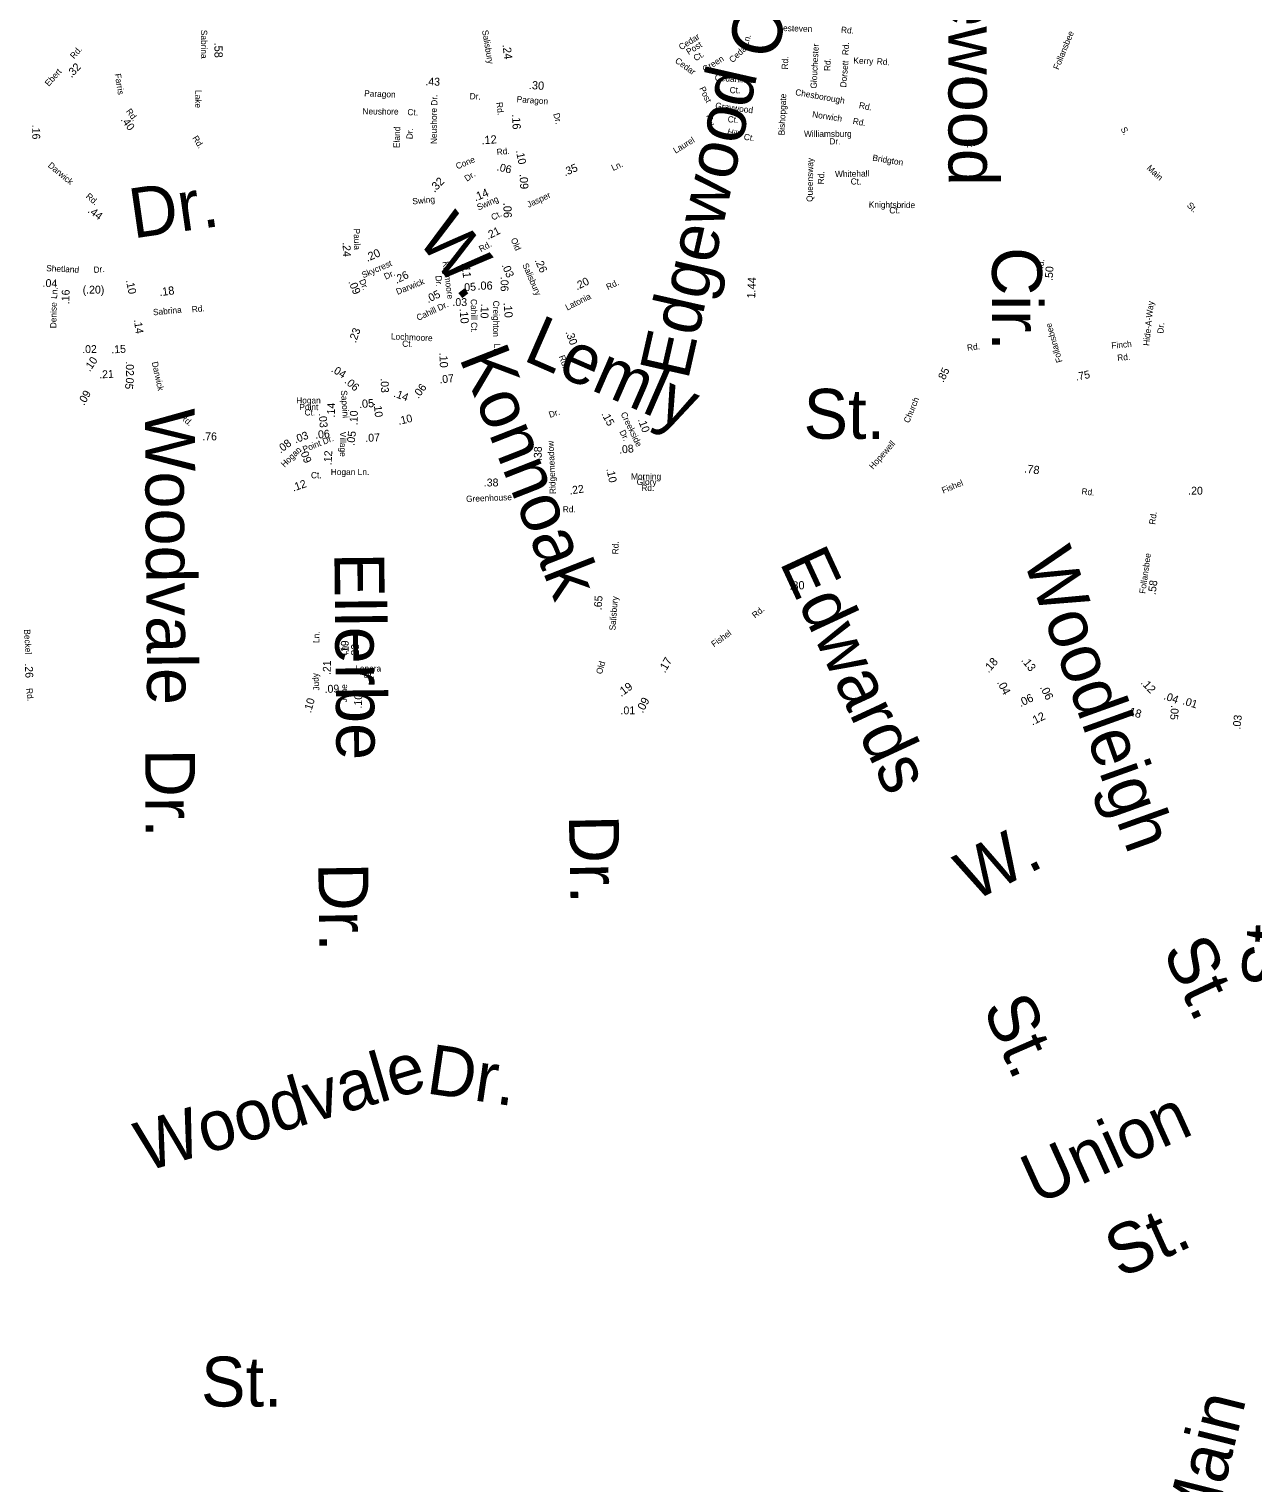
# Model space of a CAD drawing. Extents: x 1553981 to 1780076, y 812965 to 996873.
# Drawn here: x 1631447 to 1633779, y 842188 to 844957 of the extents above; entities that cross this region are included whole.
import ezdxf

# ---------------------------------------------------------------- set-up
doc = ezdxf.new("R2010")
doc.units = 0
for name, color, linetype in [('Exist Road Non-System Type 51 Label', 7, 'Continuous'), ('Exist Road Primary NC Service Mileage Hundredths English Label', 7, 'Continuous'), ('Exist Road Secondary Mileage Hundredths English Label', 7, 'Continuous'), ('Map Preparation Border Antique Large Shape', 7, 'Continuous')]:
    doc.layers.add(name, color=color, linetype=linetype)

msp = doc.modelspace()

# ---------------------------------------------------------------- texts
at = {"layer": 'Exist Road Non-System Type 51 Label'}
for s, height, rotation, p in [('Edgewood', 95, 270.0379, (1633198.2, 845258.6)), ('Cir.', 95, 77.2099, (1632869.8, 844896.5)), ('Kesteven', 11.87, 358.331, (1632872.6, 844953.4)), ('Cedar', 11.88, 32.0172, (1632689.2, 844916.4)), ('Ln.', 11.88, 73.5283, (1632816.3, 844923.9)), ('Rd.', 11.88, 356.1209, (1632993.4, 844949.8)), ('Follansbee', 11.87, 67.591, (1633408.3, 844878.5)), ('Post', 11.88, 32.0172, (1632703.4, 844907.3)), ('Ct.', 11.88, 32.0172, (1632717, 844895.3)), ('Cedar', 11.88, 42.9703, (1632787.1, 844891.9)), ('Glouchester', 11.875, 87.1504, (1632947.2, 844843.3)), ('Rd.', 11.87, 86.4361, (1633007.8, 844906.9)), ('Edgewood', 95, 77.2099, (1632702, 844286.7)), ('Cedar', 11.88, 324.0958, (1632676.3, 844894.2)), ('Green', 11.87, 31.5721, (1632734.3, 844874.3)), ('Rd.', 11.88, 87.5017, (1632892.4, 844879.8)), ('Rd.', 11.87, 87.1504, (1632973.1, 844876.8)), ('Dorsett', 11.88, 85.1235, (1633003.6, 844845.4)), ('Kerry', 11.88, 357.7706, (1633017.1, 844891.3)), ('Rd.', 11.88, 355.4178, (1633061.5, 844889.9)), ('Cedarlimb', 11.88, 355.783, (1632752.9, 844858.8)), ('Dr.', 11.88, 89.7738, (1632224.7, 844810.9)), ('Post', 11.88, 295.5736, (1632723.4, 844844)), ('Ct.', 11.87, 359.8343, (1632781.6, 844834.7)), ('Bishopgate', 11.88, 87.5649, (1632886.2, 844754.3)), ('Chesborough', 11.875, 349.9215, (1632905.9, 844831.3)), ('Neushore', 11.88, 359.7206, (1632081.9, 844794.4)), ('Ct.', 11.87, 357.8892, (1632167.4, 844793)), ('Neushore', 11.88, 89.9854, (1632223.7, 844737.8)), ('Graywood', 11.88, 352.7558, (1632753.6, 844805.5)), ('Norwich', 11.87, 351.2524, (1632938.2, 844789.1)), ('Rd.', 11.88, 348.3234, (1633027.1, 844806.6)), ('Rd.', 11.88, 277.3767, (1632737.1, 844792.8)), ('Ct.', 11.88, 356.0872, (1632777.5, 844779.5)), ('Rd.', 11.87, 349.9299, (1633015.4, 844776.3)), ('Eland', 11.88, 87.9801, (1632152.6, 844730.2)), ('Dr.', 11.88, 87.9801, (1632177.4, 844747)), ('Laurel', 11.88, 31.2119, (1632678.4, 844719.4)), ('Hill', 11.88, 343.6571, (1632775.9, 844756.6)), ('Ct.', 11.88, 351.978, (1632807.9, 844746.2)), ('Williamsburg', 11.875, 359.9662, (1632923.2, 844751.6)), ('Dr.', 11.88, 0.0292, (1632971.5, 844737.1)), ('Rd.', 11.88, 14.1286, (1633233.3, 844730.6)), ('S.', 11.88, 296.2999, (1633526.2, 844766.9)), ('Bridgton', 11.88, 350.7076, (1633052.9, 844706.4)), ('Queensway', 11.87, 89.1958, (1632939.8, 844627.7)), ('Whitehall', 11.88, 1.1444, (1632982.4, 844674.9)), ('Main', 11.88, 316.9743, (1633575.3, 844690.9)), ('Dr.', 95, 8.1495, (1631644.9, 844558)), ('Rd.', 11.87, 89.1958, (1632961.4, 844661.2)), ('Ct.', 11.88, 359.7089, (1633012.1, 844660.8)), ('W.', 95, 308.1143, (1632183.5, 844557.5)), ('Knightsbride', 11.875, 359.2377, (1633046.6, 844617)), ('Ct.', 11.88, 0.5122, (1633085.8, 844605.7)), ('St.', 11.88, 317.1411, (1633651.8, 844619.8)), ('Cir.', 95, 270.0379, (1633281.5, 844541.5)), ('Hide-A-Way', 11.88, 84.0485, (1633581, 844353.1)), ('Lemly', 95, 336.4005, (1632385.6, 844327)), ('Dr.', 11.88, 84.0485, (1633607.8, 844376.4)), ('Konnoak', 95, 291.3903, (1632265.6, 844331.1)), ('Finch', 11.87, 5.4278, (1633509.4, 844348)), ('Rd.', 11.87, 5.4278, (1633520.6, 844324.8)), ('St.', 95, 359.7227, (1632922.2, 844176.9)), ('Woodvale', 95, 270.4668, (1631667.3, 844234)), ('Edwards', 95, 294.7966, (1632875.8, 843941.6)), ('Woodleigh', 95, 289.7153, (1633339.7, 843947.9)), ('Ellerbe', 95, 270.6131, (1632028.4, 843959.4)), ('Dr.', 95, 270.2333, (1631668, 843586)), ('Dr.', 95, 271.1943, (1632475.1, 843459.2)), ('W.', 95, 26.6867, (1633244.5, 843293.8)), ('Dr.', 95, 270.7709, (1631997.7, 843368.6)), ('St.', 95, 87.3612, (1633851.6, 843128.7)), ('St.', 95, 295.054, (1633605.3, 843201.6)), ('St.', 95, 293.5348, (1633262.8, 843093.2)), ('Woodvale', 95, 16.4005, (1631667.1, 842779.8)), ('Dr.', 95, 351.5909, (1632201.4, 842930)), ('Union', 95, 24.3249, (1633366, 842716.6)), ('St.', 95, 24.3249, (1633525.4, 842576.4)), ('St.', 95, 359.8625, (1631774.3, 842333.3)), ('Main', 95, 75.9297, (1633698.9, 842079.4))]:
    msp.add_text(s, height=height, rotation=rotation, dxfattribs=at).set_placement(p)
at = {"layer": 'Exist Road Primary NC Service Mileage Hundredths English Label'}
for s, rotation, p in [('1.44', 87.2688, (1632830, 844443.4)), ('.17', 60.4535, (1632658.3, 843729.3)), ('.09', 62.259, (1632616.1, 843653))]:
    msp.add_text(s, height=15.62, rotation=rotation, dxfattribs=at).set_placement(p)
at = {"layer": 'Exist Road Secondary Mileage Hundredths English Label'}
for s, height, rotation, p in [('.58', 15.62, 270.7441, (1631799.7, 844931.1)), ('.24', 15.62, 277.5851, (1632348.6, 844927.2)), ('.32', 15, 46.939, (1631527.6, 844863.3)), ('.43', 15, 357.6901, (1632201.6, 844850.1)), ('.30', 15.62, 356.7845, (1632398.7, 844842.7)), ('.16', 15, 270.4017, (1631452.8, 844774.6)), ('.40', 15, 306.2055, (1631620.7, 844784.3)), ('.16', 15.62, 272.8269, (1632366.8, 844794.4)), ('.12', 15.62, 3.9224, (1632309.3, 844737.4)), ('.10', 15, 281.6932, (1632374.1, 844725.3)), ('.06', 15, 346.6895, (1632336.9, 844688)), ('.35', 15, 23.4834, (1632468.1, 844676.5)), ('.32', 15.62, 45.7381, (1632219.1, 844644.8)), ('.09', 15.62, 272.9207, (1632381.2, 844680.6)), ('.14', 15.62, 22.4428, (1632297.2, 844628.5)), ('.44', 15, 323.5377, (1631557.4, 844608.8)), ('.06', 15.62, 271.2232, (1632350.3, 844626)), ('.21', 15, 26.6063, (1632321.1, 844555.4)), ('.24', 15, 271.7465, (1632044.2, 844550.7)), ('.20', 15.62, 23.8157, (1632091.2, 844513.4)), ('.26', 15, 26.7807, (1632146.9, 844471.4)), ('.11', 15.62, 275.4112, (1632271, 844511)), ('.03', 15, 293.4351, (1632346.7, 844507.3)), ('.26', 15, 294.3377, (1632409.7, 844516.5)), ('.50', 15, 86.2652, (1633396.9, 844476.9)), ('.04', 15, 357.0872, (1631472.2, 844466.2)), ('(.20)', 15, 0.2502, (1631548.9, 844453)), ('.10', 15, 281.9272, (1631631.1, 844478.2)), ('.18', 15.62, 7.7266, (1631695.6, 844448)), ('.09', 15, 292.6552, (1632054.7, 844475.6)), ('.05', 15, 4.2375, (1632270.9, 844457.1)), ('.06', 15.62, 1.0194, (1632301.1, 844460.3)), ('.06', 15, 269.4393, (1632345.4, 844485.1)), ('.20', 15, 26.6549, (1632490.6, 844459.2)), ('.16', 15, 88.048, (1631523.2, 844432.7)), ('.05', 15, 26.3902, (1632207, 844434.7)), ('.03', 15, 359.9754, (1632253.4, 844429.4)), ('.10', 15.62, 274.9894, (1632266.8, 844424.2)), ('.10', 15, 267.7649, (1632307.9, 844434)), ('.10', 15.62, 273.9182, (1632351, 844435.5)), ('.14', 15, 278.1408, (1631646.4, 844403.3)), ('.23', 15, 70.0508, (1632069.2, 844358.2)), ('.30', 15, 289.8351, (1632468.6, 844379.8)), ('.02', 15, 0.7617, (1631548, 844339.7)), ('.10', 15, 55.7678, (1631562.5, 844303.2)), ('.15', 15, 3.1367, (1631603.8, 844339.1)), ('.10', 15.62, 272.2004, (1632228.4, 844340.6)), ('.21', 15, 2.8241, (1631580.7, 844291.5)), ('.02', 15, 270.5206, (1631631.2, 844324.1)), ('.04', 15, 328.3282, (1632021.2, 844305.4)), ('.85', 15, 63.4488, (1633188.7, 844282.6)), ('.75', 15, 10.8768, (1633441.9, 844287.1)), ('.05', 15, 263.1604, (1631632.6, 844299.3)), ('.06', 15, 319.2607, (1632046.7, 844284.1)), ('.03', 15, 271.4056, (1632116.7, 844291.7)), ('.06', 15, 53.4682, (1632188.5, 844252.1)), ('.07', 15, 6.5118, (1632229.2, 844281.8)), ('.09', 15, 60.0569, (1631551.5, 844239.1)), ('.05', 15.62, 4.8325, (1632075.8, 844234.7)), ('.14', 15, 340.1648, (1632140.1, 844257.1)), ('.03', 15, 274.3997, (1631998.7, 844224.9)), ('.14', 15, 88.8317, (1632029.3, 844217.1)), ('.10', 15, 89.1188, (1632072.7, 844202.5)), ('.10', 15, 275.1964, (1632103.4, 844244.7)), ('.10', 15, 13.185, (1632151.1, 844202.8)), ('.15', 15, 297.9241, (1632536.8, 844223.9)), ('.03', 15, 20.5524, (1631954.4, 844167.6)), ('.06', 15, 5.1932, (1631992.4, 844176.6)), ('.05', 15, 83.3029, (1632066.5, 844162.9)), ('.10', 15, 290.6792, (1632606.3, 844212.9)), ('.76', 15, 0.0738, (1631776.8, 844173.6)), ('.08', 15, 37.3337, (1631926, 844148.3)), ('.07', 15, 2.5253, (1632087.6, 844170.6)), ('.08', 15, 5.6151, (1632571.6, 844148.2)), ('.09', 15, 291.2546, (1631961.8, 844154.5)), ('.12', 15, 86.4956, (1632022.9, 844125.8)), ('.38', 15, 89.3789, (1632423.4, 844134.1)), ('.10', 15, 282.303, (1632546.5, 844119)), ('.78', 15.62, 352.9157, (1633342.2, 844112.3)), ('.12', 15, 19.0589, (1631950.3, 844075.9)), ('.38', 15, 0.2459, (1632313.2, 844085.7)), ('.22', 15, 8.6104, (1632477.2, 844070.3)), ('.20', 15, 359.9407, (1633655.2, 844070.2)), ('.80', 15.62, 2.4896, (1632895.6, 843888.8)), ('.58', 15, 81.979, (1633592.9, 843878.6)), ('.65', 15, 85.6226, (1632537.5, 843849.5)), ('.19', 15, 88.4734, (1632055.2, 843764.5)), ('.23', 15, 89.1025, (1632075, 843757.8)), ('.26', 15, 272.6013, (1631438.7, 843748.4)), ('.21', 15, 88.5339, (1632021.3, 843726.4)), ('.18', 15.62, 48.4946, (1633274.8, 843729.4)), ('.13', 15.62, 308.1572, (1633336.3, 843754.4)), ('.09', 15, 2.3547, (1632010.1, 843692.3)), ('.19', 15.62, 36.1796, (1632574.8, 843684.3)), ('.04', 15.62, 297.7743, (1633290.4, 843712.7)), ('.06', 15.62, 296.6175, (1633372.3, 843703.2)), ('.12', 15.62, 312.8189, (1633563.8, 843711.3)), ('.04', 15, 340.5589, (1633607.3, 843680.8)), ('.10', 15, 73.7478, (1631983.7, 843653.4)), ('.10', 15, 87.5819, (1632080.6, 843662.5)), ('.06', 15.62, 25.6624, (1633335.9, 843665.2)), ('.18', 15.62, 344.6499, (1633535.8, 843651.8)), ('.05', 15, 266.1859, (1633622.6, 843669.3)), ('.01', 15, 342.6577, (1633643.5, 843671.1)), ('.12', 15.62, 26.1719, (1633358.4, 843630.2)), ('.03', 15, 83.9232, (1633754.6, 843622.2))]:
    msp.add_text(s, height=height, rotation=rotation, dxfattribs=at).set_placement(p)
msp.add_text('.01', height=15, dxfattribs=at).set_placement((1632573.6, 843651.7))
at = {"layer": 'Map Preparation Border Antique Large Shape'}
for s, height, rotation, p in [('Sabrina', 11.88, 270.2432, (1631774.2, 844955.5)), ('Salisbury', 11.88, 279.7724, (1632309.7, 844954.1)), ('Rd.', 11.88, 49.357, (1631532.6, 844899.3)), ('Ebert', 11.88, 47.8501, (1631484.3, 844847)), ('Farris', 11.88, 279.0661, (1631609.9, 844871.3)), ('Lake', 11.87, 269.0788, (1631763.6, 844841)), ('Paragon', 11.87, 357.7569, (1632085, 844828.7)), ('Dr.', 11.88, 357.6901, (1632286, 844823.4)), ('Paragon', 11.88, 355.9727, (1632375.4, 844817.6)), ('Rd.', 11.88, 306.2053, (1631630.8, 844800.1)), ('Rd.', 11.88, 277.78, (1632336.7, 844817)), ('Dr.', 11.87, 284.9238, (1632445.3, 844795.3)), ('Rd.', 11.88, 302.0167, (1631757.4, 844749.4)), ('Rd.', 11.88, 6.1961, (1632338.3, 844716.6)), ('Darwick', 11.88, 320.1531, (1631481.6, 844695.5)), ('Cone', 11.87, 22.7756, (1632262.7, 844689.5)), ('Ln.', 11.88, 23.843, (1632559.3, 844686.5)), ('Dr.', 11.88, 34.0441, (1632281.1, 844665.9)), ('Rd.', 11.88, 319.1628, (1631553.8, 844636.8)), ('Swing', 11.88, 5.5441, (1632177.5, 844622.9)), ('Swing', 11.88, 24.1941, (1632303.1, 844611.3)), ('Jasper', 11.88, 25.2653, (1632398.7, 844616.4)), ('Ct.', 11.88, 27.2462, (1632330.7, 844592)), ('Paula', 11.87, 271.7465, (1632065, 844576.8)), ('Rd.', 11.88, 29.2143, (1632307.8, 844531.8)), ('Old', 11.88, 293.4114, (1632364.1, 844556.3)), ('Shetland', 11.87, 357.0871, (1631479.2, 844495.8)), ('Dr.', 11.88, 6.5508, (1631570.3, 844492.2)), ('Skycrest', 11.88, 23.4831, (1632083.4, 844482.2)), ('Dr.', 11.88, 24.8022, (1632126.2, 844479.4)), ('Kaymoore ', 11.88, 277.5527, (1632234.5, 844513.7)), ('Salisbury', 11.88, 293.765, (1632386.1, 844507.9)), ('Rd.', 11.88, 81.9835, (1633377.9, 844493.5)), ('Dr.', 11.87, 292.6552, (1632075.3, 844477.9)), ('Darwick', 11.88, 21.8754, (1632148.8, 844450.6)), ('Dr.', 11.88, 274.7554, (1632220.8, 844486.9)), ('Rd.', 11.87, 25.7479, (1632549.8, 844459.5)), ('Ln.', 11.88, 86.6509, (1631500, 844442.8)), ('Cahill Ct.', 11.88, 270.5968, (1632288.3, 844442.7)), ('Latonia', 11.88, 26.6549, (1632472.1, 844420.6)), ('Denise', 11.88, 89.1195, (1631498.7, 844387)), ('Sabrina', 11.88, 5.2821, (1631683.4, 844411.6)), ('Rd.', 11.88, 5.1641, (1631757.2, 844417.1)), ('Cahill Dr.', 11.87, 25.0654, (1632188.1, 844401)), ('Creighton', 11.88, 270, (1632330.8, 844439.6)), ('Follansbee', 11.88, 106.1884, (1633415.8, 844323.4)), ('Lochmoore ', 11.87, 357.4091, (1632136, 844365.9)), ('Ln.', 11.88, 270, (1632332.7, 844357.8)), ('Rd.', 11.87, 7.7003, (1633234.6, 844343.9)), ('Rd.', 11.88, 290.0014, (1632455.7, 844333.3)), ('Darwick', 11.88, 282.2411, (1631680.4, 844322.2)), ('Sapoini', 11.88, 274.0826, (1632040.8, 844268.6)), ('Church', 11.88, 67.3578, (1633123.4, 844205.5)), ('Rd.', 11.88, 318.208, (1631733.7, 844216.3)), ('Dr.', 11.88, 18.6149, (1632439.3, 844216.2)), ('Creekside', 11.88, 295.8444, (1632573.5, 844224.2)), ('Village', 11.88, 270, (1632039, 844190)), ('Dr.', 11.87, 296.1139, (1632571.1, 844190)), ('Point Dr.', 11.88, 21.5162, (1631970.8, 844150.3)), ('Ridgemeadow', 11.875, 92.4871, (1632450.5, 844071.5)), ('Hopewell', 11.88, 48.4974, (1633054.7, 844117.5)), ('Hogan ', 11.88, 45.0205, (1631933.6, 844121.3)), ('Fishel', 11.88, 22.5521, (1633188.5, 844072)), ('Rd.', 11.87, 353.7723, (1633451.5, 844070.8)), ('Greenhouse', 11.88, 2.3249, (1632279.6, 844056.1)), ('Rd.', 11.88, 0.4246, (1632463.7, 844036.2)), ('Rd.', 11.88, 81.9835, (1633592.1, 844012.5)), ('Rd.', 11.88, 89.1481, (1632569.7, 843956.4)), ('Follansbee', 11.87, 81.979, (1633573.5, 843880.9)), ('Salisbury', 11.88, 85.6226, (1632563.8, 843811.1)), ('Rd.', 11.88, 39.6819, (1632830.1, 843834)), ('Beckel', 11.88, 272.9991, (1631437.2, 843813.4)), ('Ln.', 11.88, 87.9064, (1631999.5, 843787.3)), ('Fishel', 11.87, 35.6073, (1632751.7, 843779.1)), ('Ln.', 11.88, 88.3324, (1632052.6, 843764.2)), ('Old', 11.88, 74.0922, (1632538.1, 843727.2)), ('Judy', 11.88, 94.3574, (1632000.1, 843697.2)), ('Rd.', 11.88, 276.6555, (1631441.1, 843700.9)), ('June', 11.88, 89.7531, (1632052.6, 843674.5))]:
    msp.add_text(s, height=height, rotation=rotation, dxfattribs=at).set_placement(p)
for s, p in [('Ct. ', (1632157.7, 844351.7)), ('Hogan', (1631955.7, 844243.8)), ('Point', (1631961.7, 844231.1)), ('Ct.', (1631971.6, 844220.9)), ('Ct.', (1631983.8, 844101.3)), ('Hogan Ln.', (1632021.6, 844107.4)), ('Morning', (1632593.6, 844098.9)), ('Glory', (1632604.4, 844088.5)), ('Rd.', (1632613.3, 844077)), ('Lenora', (1632068.1, 843733.2)), ('Dr.', (1632083.9, 843721.5))]:
    msp.add_text(s, height=11.88, dxfattribs=at).set_placement(p)

doc.saveas('drawing.dxf')
